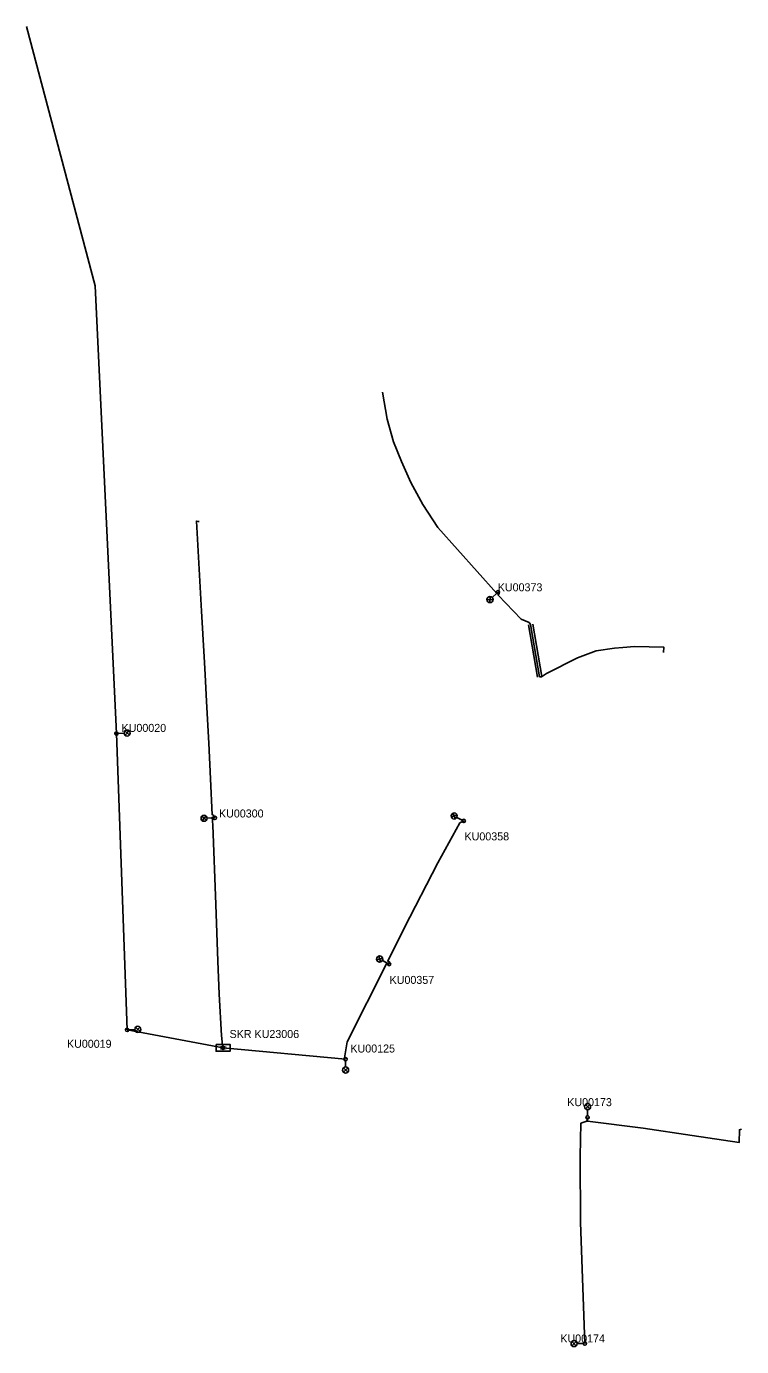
# Model space of a CAD drawing. Extents: x -727792 to -727658, y -1063536 to -1063043.
# Drawn here: x -727792.1 to -727657.9, y -1063290.9 to -1063043.4 of the extents above; entities that cross this region are included whole.
import ezdxf

# ---------------------------------------------------------------- set-up
doc = ezdxf.new("R2010")
doc.units = 0
for name, color, linetype in [('Chranicka', 7, 'Continuous'), ('Delici_skrin', 7, 'Continuous'), ('Delici_skrin_popis', 7, 'Continuous'), ('Kabelove_vedeni_vrchni', 7, 'Continuous'), ('Kabelove_vedeni_zemni', 7, 'Continuous'), ('Pomocny_stozar', 7, 'Continuous'), ('Verejne_osvetleni', 7, 'Continuous'), ('Verejne_osvetleni_popis', 7, 'Continuous')]:
    doc.layers.add(name, color=color, linetype=linetype)

msp = doc.modelspace()

# ---------------------------------------------------------------- linework, layer by layer
at = {"layer": 'Chranicka'}
for points in [[(-727696.22, -1063165.4), (-727697.91, -1063155.61)], [(-727695.44, -1063165.26), (-727697.13, -1063155.47)]]:
    msp.add_lwpolyline(points, dxfattribs=at)
at = {"layer": 'Delici_skrin'}
msp.add_lwpolyline([(-727756.5, -1063234.23), (-727753.9, -1063234.23), (-727753.9, -1063235.53), (-727756.5, -1063235.53)], close=True, dxfattribs=at)
at = {"layer": 'Kabelove_vedeni_vrchni'}
for points in [[(-727792.09, -1063043.45), (-727779.2, -1063092.04), (-727775.21, -1063175.98)], [(-727775.21, -1063175.98), (-727773.21, -1063231.51)], [(-727773.21, -1063231.51), (-727755.2, -1063234.88)], [(-727755.2, -1063234.88), (-727732.22, -1063237.01)]]:
    msp.add_lwpolyline(points, dxfattribs=at)
at = {"layer": 'Kabelove_vedeni_zemni'}
for points in [[(-727725.32, -1063112.02), (-727724.45, -1063117.04), (-727723.21, -1063121.33), (-727721.76, -1063125.02), (-727720, -1063128.96), (-727717.73, -1063133.05), (-727714.93, -1063137.34), (-727703.87, -1063149.71), (-727703.66, -1063149.5)], [(-727756.72, -1063191.79), (-727756.97, -1063191.28), (-727757.25, -1063191.19), (-727757.57, -1063184.49), (-727757.9, -1063177.76), (-727758.3, -1063169.98), (-727758.57, -1063164.91), (-727758.74, -1063161.58), (-727759.23, -1063153.02), (-727760.2, -1063136.17), (-727759.9, -1063136.21), (-727759.7, -1063136.24)], [(-727703.66, -1063149.5), (-727703.45, -1063149.85), (-727703.61, -1063150.02), (-727699.3, -1063154.53), (-727697.8, -1063155.19), (-727697.52, -1063155.54), (-727695.83, -1063165.33), (-727695.49, -1063165.38), (-727694.56, -1063164.71), (-727688.75, -1063161.81), (-727685.23, -1063160.49), (-727681.77, -1063159.96), (-727680.25, -1063159.83), (-727678.05, -1063159.65), (-727672.56, -1063159.77), (-727672.63, -1063160.8)], [(-727755.2, -1063234.88), (-727755.25, -1063234.87), (-727755.25, -1063234.86), (-727755.24, -1063234.86), (-727755.24, -1063234.85), (-727755.23, -1063234.84), (-727755.23, -1063234.84), (-727755.22, -1063234.83), (-727755.21, -1063234.83), (-727755.24, -1063234.73), (-727755.26, -1063234.64), (-727755.32, -1063234.37), (-727755.47, -1063232.6), (-727755.95, -1063224.81), (-727756.18, -1063218.62), (-727756.57, -1063208.02), (-727757.12, -1063193.14), (-727757.23, -1063191.62), (-727756.91, -1063191.73), (-727756.72, -1063191.79)], [(-727724.05, -1063219.2), (-727724, -1063218.78), (-727724.33, -1063218.64), (-727721.26, -1063212.47), (-727714.9, -1063200.2), (-727710.77, -1063192.73), (-727710.06, -1063192.36)], [(-727732.22, -1063237.01), (-727732.44, -1063236.89), (-727732.42, -1063236.76), (-727731.91, -1063233.73), (-727724.5, -1063219), (-727724.05, -1063219.2)], [(-727687.34, -1063290.3), (-727688.18, -1063267.63), (-727688.22, -1063255.25), (-727688.08, -1063249.03), (-727686.96, -1063248.6), (-727686.84, -1063247.91)], [(-727686.84, -1063247.91), (-727686.84, -1063248.61), (-727676.4, -1063249.91), (-727667.2, -1063251.3), (-727658.39, -1063252.62), (-727658.35, -1063250.24), (-727657.95, -1063250.1)]]:
    msp.add_lwpolyline(points, dxfattribs=at)
at = {"layer": 'Pomocny_stozar'}
msp.add_circle((-727755.2, -1063234.88), 0.305, dxfattribs=at)
at = {"layer": 'Verejne_osvetleni'}
for p, q in [((-727705.72, -1063150.85), (-727704.58, -1063150.9)), ((-727705.18, -1063151.45), (-727705.13, -1063150.3)), ((-727703.89, -1063149.71), (-727704.73, -1063150.48)), ((-727774.9, -1063175.96), (-727773.76, -1063175.91)), ((-727772.76, -1063176.28), (-727773.61, -1063175.5)), ((-727772.8, -1063175.47), (-727773.57, -1063176.31)), ((-727712.41, -1063191.61), (-727711.32, -1063191.26)), ((-727712.04, -1063190.89), (-727711.69, -1063191.98)), ((-727759.16, -1063191.46), (-727758.33, -1063192.24)), ((-727759.14, -1063192.27), (-727758.35, -1063191.43)), ((-727757.03, -1063191.8), (-727758.17, -1063191.83)), ((-727710.33, -1063192.22), (-727711.35, -1063191.7)), ((-727726.39, -1063218.41), (-727725.29, -1063218.08)), ((-727726, -1063217.7), (-727725.67, -1063218.79)), ((-727724.32, -1063219.06), (-727725.33, -1063218.52)), ((-727772.91, -1063231.5), (-727771.76, -1063231.45)), ((-727770.77, -1063231.81), (-727771.61, -1063231.03)), ((-727770.8, -1063231), (-727771.58, -1063231.84)), ((-727732.22, -1063237.32), (-727732.23, -1063238.46)), ((-727732.64, -1063239.44), (-727731.82, -1063238.63)), ((-727731.82, -1063239.44), (-727732.63, -1063238.63)), ((-727687.25, -1063245.48), (-727686.43, -1063246.29)), ((-727686.43, -1063245.48), (-727687.25, -1063246.29)), ((-727686.84, -1063247.6), (-727686.84, -1063246.46)), ((-727689.77, -1063290.71), (-727688.96, -1063289.89)), ((-727689.77, -1063289.89), (-727688.96, -1063290.71)), ((-727687.65, -1063290.3), (-727688.79, -1063290.3))]:
    msp.add_line(p, q, dxfattribs=at)
for centre, radius in [((-727703.66, -1063149.5), 0.306), ((-727705.15, -1063150.87), 0.574), ((-727775.21, -1063175.98), 0.306), ((-727773.19, -1063175.89), 0.574), ((-727758.75, -1063191.85), 0.574), ((-727711.86, -1063191.43), 0.574), ((-727756.72, -1063191.79), 0.306), ((-727710.06, -1063192.36), 0.306), ((-727725.84, -1063218.24), 0.574), ((-727724.05, -1063219.2), 0.306), ((-727771.19, -1063231.42), 0.574), ((-727773.21, -1063231.51), 0.306), ((-727732.22, -1063237.01), 0.306), ((-727732.23, -1063239.04), 0.574), ((-727686.84, -1063245.88), 0.574), ((-727686.84, -1063247.91), 0.306), ((-727689.37, -1063290.3), 0.574), ((-727687.34, -1063290.3), 0.306)]:
    msp.add_circle(centre, radius, dxfattribs=at)

# ---------------------------------------------------------------- texts
at = {"layer": 'Delici_skrin'}
msp.add_text('DS', height=0.65, dxfattribs=at).set_placement((-727755.77, -1063235.2))
at = {"layer": 'Delici_skrin_popis'}
msp.add_text('SKR KU23006', height=1.5, dxfattribs=at).set_placement((-727753.98, -1063233.04))
at = {"layer": 'Verejne_osvetleni_popis'}
for s, p in [('KU00373', (-727703.68, -1063149.32)), ('KU00020', (-727774.24, -1063175.67)), ('KU00300', (-727755.97, -1063191.71)), ('KU00358', (-727709.92, -1063196)), ('KU00357', (-727723.97, -1063222.9)), ('KU00019', (-727784.48, -1063234.87)), ('KU00125', (-727731.32, -1063235.76)), ('KU00173', (-727690.65, -1063245.81)), ('KU00174', (-727691.95, -1063290.1))]:
    msp.add_text(s, height=1.5, dxfattribs=at).set_placement(p)

doc.saveas('drawing.dxf')
